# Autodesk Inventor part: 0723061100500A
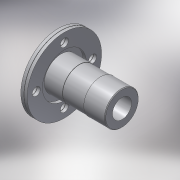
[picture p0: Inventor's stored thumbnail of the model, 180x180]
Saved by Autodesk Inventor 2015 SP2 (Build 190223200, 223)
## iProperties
Created: 2017-02
Part Number: 0723061100500A
Material: PVC-Piping
Description: PLASSON FLANGE ADAPTOR WITH METAL FLANGE 110-5"
Document SubType Name: Modeling
Designer: KIM
Mass: 92.6774 g
Surface Area: 199.44 cm^2
Volume: 66.1981 cm^3
Density: 1.4 g/cm^3
Appearance: Smooth - White
Author: Кирилл
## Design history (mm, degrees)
derived "872306.ipt"
feature "Solid1::872306.ipt"
tag "TaggingFeature1"
body "Solid1"
other parameters: "d73" = 21.4, "d74" = 90 deg, "d75" = 0.3, "d77" = 18, "d78" = 105, "d80" = 0, "d82" = 360 deg, "d94" = 125, "d96" = 0.3, "d99" = 360 deg, "d103" = 214, "d104" = 2.2, "d107" = 143, "d108" = 5.35, "d116" = 107.8, "d117" = 71.33333, "d118" = 71.33333, "d120" = 16.5, "H_" = 214, "S_" = 18, "DN_" = 125
